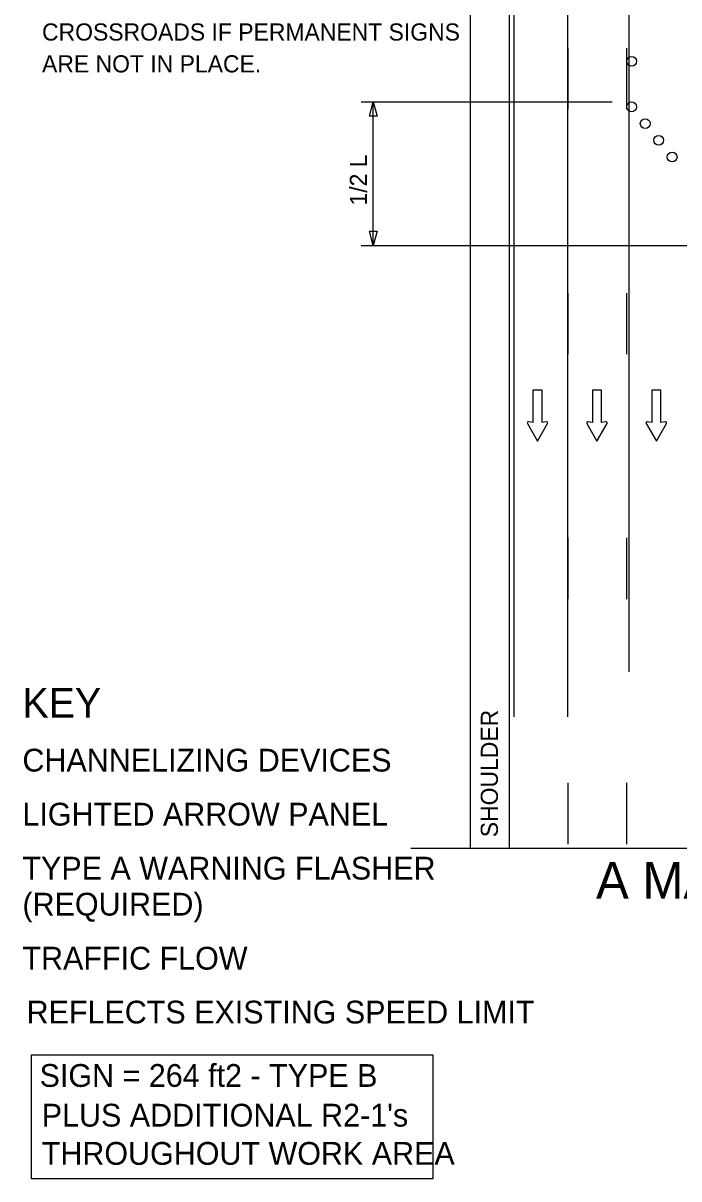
# Model space of a CAD drawing. Extents: x 16038 to 19504, y 5920 to 8321.
# Drawn here: x 16787.9 to 17055.6, y 7244.6 to 7716.4 of the extents above; entities that cross this region are included whole.
import ezdxf

# ---------------------------------------------------------------- set-up
doc = ezdxf.new("R2010")
doc.units = 0
for name, color, linetype in [('ALI_LEGAL_EX', 7, 'Continuous'), ('MT_SCRATCH_LEVEL_E', 7, 'Continuous'), ('PAVT_EDGE_EX', 7, 'Continuous'), ('TRAFFIC_SIGNS_PR', 7, 'Continuous'), ('TYPICAL_TEXT_DIMEN_EX', 7, 'Continuous'), ('TYPICAL_TEXT_DIMEN_PR', 7, 'Continuous')]:
    doc.layers.add(name, color=color, linetype=linetype)

msp = doc.modelspace()

# ---------------------------------------------------------------- linework, layer by layer
at = {"layer": 'ALI_LEGAL_EX'}
for points in [[(17010.3, 7681.21), (17010.3, 7706.21)], [(17034.3, 7681.21), (17034.3, 7706.21)], [(17010.3, 7581.21), (17010.3, 7606.21)], [(17034.3, 7581.21), (17034.3, 7606.21)], [(17010.3, 7481.21), (17010.3, 7506.21)], [(17034.3, 7481.21), (17034.3, 7506.21)], [(17010.3, 7381.21), (17010.3, 7406.21)], [(17034.3, 7381.21), (17034.3, 7406.21)]]:
    msp.add_lwpolyline(points, dxfattribs=at)
at = {"layer": 'MT_SCRATCH_LEVEL_E'}
for p, q in [((16999.71, 7566.6), (16995.97, 7566.6)), ((16995.97, 7566.6), (16995.97, 7553.34)), ((16999.71, 7566.6), (16995.97, 7566.6)), ((16995.97, 7566.6), (16995.97, 7553.34)), ((16999.71, 7553.34), (16999.71, 7566.6)), ((16999.71, 7553.34), (16999.71, 7566.6)), ((17023.97, 7566.6), (17020.23, 7566.6)), ((17020.23, 7566.6), (17020.23, 7553.34)), ((17023.97, 7566.6), (17020.23, 7566.6)), ((17020.23, 7566.6), (17020.23, 7553.34)), ((17023.97, 7553.34), (17023.97, 7566.6)), ((17023.97, 7553.34), (17023.97, 7566.6)), ((17048.23, 7566.6), (17044.48, 7566.6)), ((17044.48, 7566.6), (17044.48, 7553.34)), ((17048.23, 7566.6), (17044.48, 7566.6)), ((17044.48, 7566.6), (17044.48, 7553.34)), ((17048.23, 7553.34), (17048.23, 7566.6)), ((17048.23, 7553.34), (17048.23, 7566.6)), ((16993.72, 7552.97), (16997.86, 7545.73)), ((16993.72, 7552.97), (16997.86, 7545.73)), ((16995.97, 7553.34), (16994.19, 7553.66)), ((16995.97, 7553.34), (16994.19, 7553.66)), ((16997.86, 7545.73), (17001.97, 7552.97)), ((16997.86, 7545.73), (17001.97, 7552.97)), ((17001.49, 7553.66), (16999.71, 7553.34)), ((17001.49, 7553.66), (16999.71, 7553.34)), ((17017.97, 7552.97), (17022.12, 7545.73)), ((17017.97, 7552.97), (17022.12, 7545.73)), ((17020.23, 7553.34), (17018.45, 7553.66)), ((17020.23, 7553.34), (17018.45, 7553.66)), ((17022.12, 7545.73), (17026.23, 7552.97)), ((17022.12, 7545.73), (17026.23, 7552.97)), ((17025.75, 7553.66), (17023.97, 7553.34)), ((17025.75, 7553.66), (17023.97, 7553.34)), ((17042.23, 7552.97), (17046.37, 7545.73)), ((17042.23, 7552.97), (17046.37, 7545.73)), ((17044.48, 7553.34), (17042.71, 7553.66)), ((17044.48, 7553.34), (17042.71, 7553.66)), ((17046.37, 7545.73), (17050.49, 7552.97)), ((17046.37, 7545.73), (17050.49, 7552.97)), ((17050, 7553.66), (17048.23, 7553.34)), ((17050, 7553.66), (17048.23, 7553.34))]:
    msp.add_line(p, q, dxfattribs=at)
for centre, start, end in [((16994.12, 7553.2), 80.0362, 209.7731), ((16994.12, 7553.2), 80.0362, 209.7731), ((17001.57, 7553.2), 330.4248, 99.9638), ((17001.57, 7553.2), 330.4248, 99.9638), ((17018.38, 7553.2), 80.0362, 209.7731), ((17018.38, 7553.2), 80.0362, 209.7731), ((17025.82, 7553.2), 330.4248, 99.9638), ((17025.82, 7553.2), 330.4248, 99.9638), ((17042.64, 7553.2), 80.0362, 209.7731), ((17042.64, 7553.2), 80.0362, 209.7731), ((17050.08, 7553.2), 330.4248, 99.9638), ((17050.08, 7553.2), 330.4248, 99.9638)]:
    msp.add_arc(centre, 0.463, start, end, dxfattribs=at)
at = {"layer": 'PAVT_EDGE_EX'}
for p, q in [((17035.15, 8280.7), (17035.15, 7451.51)), ((16988.15, 8262.34), (16988.15, 7433.15)), ((17010.15, 8262.34), (17010.15, 7433.15)), ((16970.3, 8211.37), (16970.3, 7379.53)), ((16986.3, 8211.37), (16986.3, 7379.53))]:
    msp.add_line(p, q, dxfattribs=at)
at = {"layer": 'TRAFFIC_SIGNS_PR'}
for centre in [(17036.3, 7700.81), (17036.3, 7682.22), (17041.8, 7675.39), (17047.3, 7668.56), (17052.8, 7661.73)]:
    msp.add_circle(centre, 2, dxfattribs=at)
at = {"layer": 'TYPICAL_TEXT_DIMEN_EX'}
msp.add_lwpolyline([(16791.27, 7295.24), (16955.12, 7295.24), (16955.12, 7244.56), (16791.27, 7244.56)], close=True, dxfattribs=at)
at = {"layer": 'TYPICAL_TEXT_DIMEN_PR'}
for p, q in [((16925.8, 7684.22), (17028.29, 7684.22)), ((16929.23, 7678.36), (16930.8, 7684.22)), ((16930.8, 7625.58), (16930.8, 7684.22)), ((16930.8, 7684.22), (16932.37, 7678.36)), ((16930.8, 7678.36), (16929.23, 7678.36)), ((16932.37, 7678.36), (16930.8, 7678.36)), ((16930.8, 7625.58), (16929.23, 7631.44)), ((16929.23, 7631.44), (16930.8, 7631.44)), ((16930.8, 7631.44), (16932.37, 7631.44)), ((16932.37, 7631.44), (16930.8, 7625.58)), ((16925.8, 7625.58), (17074.05, 7625.58)), ((16946.19, 7379.53), (17187.1, 7379.53))]:
    msp.add_line(p, q, dxfattribs=at)

# ---------------------------------------------------------------- texts
at = {"layer": 'TRAFFIC_SIGNS_PR'}
for s, p in [('CROSSROADS IF PERMANENT SIGNS', (16795.6, 7709.28)), ('ARE NOT IN PLACE.', (16795.6, 7696.28))]:
    msp.add_text(s, height=7, dxfattribs=at).set_placement(p)
at = {"layer": 'TYPICAL_TEXT_DIMEN_EX'}
for s, height, p in [('KEY', 12, (16787.6, 7432.9)), ('CHANNELIZING DEVICES', 9.3, (16787.6, 7410.85)), ('LIGHTED ARROW PANEL', 9.3, (16787.6, 7388.8)), ('TYPE A WARNING FLASHER', 9.3, (16787.6, 7366.75)), ('(REQUIRED)', 9.3, (16787.6, 7352.05)), ('TRAFFIC FLOW', 9.3, (16787.6, 7330)), ('REFLECTS EXISTING SPEED LIMIT', 9.3, (16789.29, 7308)), ('SIGN = 264 ft2 - TYPE B', 9.3, (16794.61, 7282.12)), ("PLUS ADDITIONAL R2-1's", 9.3, (16795.48, 7265.91)), ('THROUGHOUT WORK AREA', 9.3, (16795.48, 7250.31))]:
    msp.add_text(s, height=height, dxfattribs=at).set_placement(p)
at = {"layer": 'TYPICAL_TEXT_DIMEN_PR'}
for s, p in [('1/2 L', (16928.24, 7641.94)), ('SHOULDER', (16981.68, 7384.04))]:
    msp.add_text(s, height=7, rotation=90, dxfattribs=at).set_placement(p)
msp.add_text('A MATCH A', height=15, dxfattribs=at).set_placement((17021.72, 7358.96))

doc.saveas('drawing.dxf')
